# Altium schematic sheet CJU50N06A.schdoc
size 127 x 101 mm
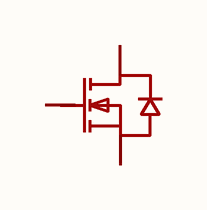
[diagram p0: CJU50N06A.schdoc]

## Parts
U?  cju50n06a  [TO-252-2_L6.6-W6.1-P4.57-LS10.0-BR-1]  (value not drawn)

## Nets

Not connected (* = marked no-connect by the designer): U? 1(G) 2(D) 3(S)

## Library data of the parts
U? = cju50n06a: 数量:1个N沟道;漏源电压(Vdss):60V;连续漏极电流(Id):50A;导通电阻(RDS(on)):25mΩ@4.5V;耗散功率(Pd):75W;阈值电压(Vgs(th)):2.5V;; Manufacturer: CJ(江苏长电/长晶); AddInBom: yes; ModelId: 4113ec4a058842b08e2585e7304bd9b4; ModelTransform: 401.574,259.842,0,0,0,0,-36.417,0,0; Number: 1个N沟道; Drain to Source Voltage: 60V; Current - Continuous Drain(Id): 50A; Pd - Power Dissipation: 75W; Gate Threshold Voltage (Vgs(th)): 2.5V; Gate Charge(Qg): 56nC@10V; Input Capacitance(Ciss): 3.4nF; Reverse Transfer Capacitance (Crss@Vds): 220pF; Output Capacitance(Coss): 240pF; Vgs: ±20V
